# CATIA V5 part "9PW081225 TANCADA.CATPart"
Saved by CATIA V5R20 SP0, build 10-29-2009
Part number: 9PW081225 TANCADA
Revision: ANY
Definition: UNKNOWN
Nomenclature: 9PW081225 TANCADA
Source: Unknown
Bounding box of the stored display mesh (mm): x -140 to 0, y -6.999 to 4.5, z -6.1 to 6.1
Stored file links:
  C:\Users\Utente\Desktop\IO LAVORO\3D X SITO CF\CUMSA\3D files PW\pw081225\pw081225_injection\9PW081225 TANCADA.CATPart
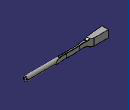
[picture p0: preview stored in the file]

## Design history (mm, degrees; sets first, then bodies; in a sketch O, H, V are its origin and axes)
Body1 "Chaflán2" (main body)
  Solid1: solid without history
